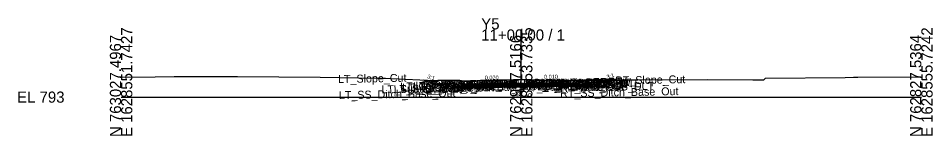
# Model space of a CAD drawing. Extents: x -26 to 203, y -10 to 6017.
# Drawn here: x -25.7 to 202.8, y 1990.3 to 2019.8 of the extents above; entities that cross this region are included whole.
import ezdxf

# ---------------------------------------------------------------- set-up
doc = ezdxf.new("R2010")
doc.units = 0
for name, color, linetype in [('Default', 7, 'Continuous'), ('Exist Cross Section Cell', 7, 'Continuous'), ('Exist XS Center Line Elevation Label', 7, 'Continuous'), ('Exist XS Ground Line', 7, 'Continuous'), ('Prop CMT Concrete Structures', 7, 'Continuous'), ('Prop CMT Pvmt Course 1', 7, 'Continuous'), ('Prop CMT Pvmt Course 2', 7, 'Continuous'), ('Prop CMT Pvmt Course 2 Wedge', 7, 'Continuous'), ('Prop CMT Pvmt Course 3', 7, 'Continuous'), ('Prop CMT Pvmt Course 3 Wedge', 7, 'Continuous'), ('Prop CMT Pvmt Surface', 7, 'Continuous'), ('Prop CMT Pvmt Surface Shoulder', 7, 'Continuous'), ('Prop CMT Pvmt Wedge Surface 2', 7, 'Continuous'), ('Prop CMT Pvmt Wedge Surface 3', 7, 'Continuous'), ('Prop CMT Shld Paved Course 1', 7, 'Continuous'), ('Prop CMT Shld Paved Course 2', 7, 'Continuous'), ('Prop CMT Shld Paved Course 3', 7, 'Continuous'), ('Prop CMT Slope Grass', 7, 'Continuous'), ('Prop CMT Subgrade Earthwork', 7, 'Continuous'), ('Prop XS SE Text', 7, 'Continuous'), ('Prop XS Side Slope Text', 7, 'Continuous'), ('Scratch_Level_0', 7, 'Continuous')]:
    doc.layers.add(name, color=color, linetype=linetype)

msp = doc.modelspace()

# ---------------------------------------------------------------- linework, layer by layer
at = {"layer": 'Exist Cross Section Cell'}
for p, q in [((100, 2000), (100, 2016.98)), ((0, 2000), (100, 2000)), ((100, 2000), (200, 2000))]:
    msp.add_line(p, q, dxfattribs=at)
at = {"layer": 'Exist XS Ground Line'}
msp.add_lwpolyline([(0, 2005.03), (8.53, 2005.09), (13.27, 2005.14), (29.06, 2005.14), (49.75, 2005), (64.15, 2004.73), (65.77, 2004.73), (66.1, 2004.74), (67.48, 2004.66), (74.7, 2004.31), (78.5, 2004.15), (79.12, 2004.21), (84.63, 2004.27), (85.57, 2004.05), (90.57, 2004.2), (98.03, 2004.44), (100, 2004.4), (113.3, 2004.16), (114.38, 2004.15), (115.84, 2004.18), (123.61, 2004.34), (129.16, 2004.36), (146.55, 2004.4), (157.88, 2004.33), (160.64, 2004.36), (161.06, 2004.79), (180.96, 2004.94), (183.03, 2004.97), (184.15, 2004.97), (200, 2005.09)], dxfattribs=at)
at = {"layer": 'Prop CMT Concrete Structures'}
for points in [[(83.35, 2003.24), (83.35, 2002.66), (85.35, 2002.66)], [(85.35, 2003.24), (84.35, 2003.16), (83.35, 2003.24)], [(85.35, 2002.66), (85.35, 2003.24)], [(114.68, 2003.1), (114.68, 2003.68)], [(116.68, 2003.68), (116.68, 2003.1), (114.68, 2003.1)], [(114.68, 2003.68), (115.68, 2003.6), (116.68, 2003.68)]]:
    msp.add_lwpolyline(points, dxfattribs=at)
at = {"layer": 'Prop CMT Pvmt Course 1'}
for points in [[(100, 2003.53), (85.35, 2003.24)], [(85.35, 2002.99), (100, 2003.28)], [(85.35, 2003.24), (85.35, 2002.99)], [(100, 2003.53), (85.57, 2003.25)], [(100, 2003.53), (114.38, 2003.68)], [(100, 2003.53), (114.68, 2003.68)], [(100, 2003.41), (100, 2003.53)], [(100, 2003.28), (100, 2003.53)], [(100, 2003.41), (100, 2003.53)], [(100, 2003.28), (100, 2003.53)], [(114.68, 2003.43), (100, 2003.28)], [(114.68, 2003.68), (114.68, 2003.43)]]:
    msp.add_lwpolyline(points, dxfattribs=at)
at = {"layer": 'Prop CMT Pvmt Course 2'}
for points in [[(100, 2003.28), (85.35, 2002.99)], [(85.35, 2002.99), (85.35, 2002.66)], [(85.35, 2002.99), (85.35, 2002.66)], [(85.35, 2002.66), (100, 2002.95)], [(100, 2003.28), (114.68, 2003.43)], [(100, 2002.95), (100, 2003.28)], [(100, 2002.95), (100, 2003.28)], [(114.68, 2003.1), (100, 2002.95)], [(114.68, 2003.43), (114.68, 2003.1)]]:
    msp.add_lwpolyline(points, dxfattribs=at)
at = {"layer": 'Prop CMT Pvmt Course 2 Wedge'}
for points in [[(100, 2003.28), (85.57, 2003)], [(100, 2003.28), (114.38, 2003.43)]]:
    msp.add_lwpolyline(points, dxfattribs=at)
at = {"layer": 'Prop CMT Pvmt Course 3'}
msp.add_line((116.68, 2003.1), (117.18, 2003.1), dxfattribs=at)
for points in [[(100, 2002.95), (85.35, 2002.66)], [(85.35, 2002.66), (85.35, 2002.32)], [(85.35, 2002.32), (100, 2002.62)], [(100, 2002.95), (114.68, 2003.1)], [(100, 2002.62), (100, 2002.95)], [(100, 2002.62), (100, 2002.95)], [(114.68, 2002.76), (100, 2002.62)], [(114.68, 2003.1), (114.68, 2002.76)]]:
    msp.add_lwpolyline(points, dxfattribs=at)
at = {"layer": 'Prop CMT Pvmt Course 3 Wedge'}
for points in [[(100, 2002.95), (85.57, 2002.66)], [(100, 2002.95), (114.38, 2003.09)]]:
    msp.add_lwpolyline(points, dxfattribs=at)
at = {"layer": 'Prop CMT Pvmt Surface'}
for points in [[(100, 2003.53), (85.35, 2003.24)], [(100, 2003.53), (85.57, 2003.25)], [(100, 2003.53), (114.68, 2003.68)], [(100, 2003.53), (114.38, 2003.68)]]:
    msp.add_lwpolyline(points, dxfattribs=at)
at = {"layer": 'Prop CMT Pvmt Surface Shoulder'}
for points in [[(85.35, 2003.24), (85.35, 2003.24)], [(114.68, 2003.68), (114.68, 2003.68)]]:
    msp.add_lwpolyline(points, dxfattribs=at)
at = {"layer": 'Prop CMT Pvmt Wedge Surface 2'}
for points in [[(100, 2003.28), (85.57, 2003)], [(100, 2003.28), (100, 2003.53)], [(100, 2003.28), (100, 2003.53)], [(100, 2003.28), (100, 2003.53)], [(100, 2003.28), (100, 2003.53)], [(100, 2003.28), (114.38, 2003.43)]]:
    msp.add_lwpolyline(points, dxfattribs=at)
at = {"layer": 'Prop CMT Pvmt Wedge Surface 3'}
for points in [[(100, 2002.95), (85.57, 2002.66)], [(100, 2002.95), (100, 2003.53)], [(100, 2002.95), (100, 2003.53)], [(100, 2002.95), (100, 2003.53)], [(100, 2002.95), (100, 2003.53)], [(100, 2002.95), (114.38, 2003.09)]]:
    msp.add_lwpolyline(points, dxfattribs=at)
at = {"layer": 'Prop CMT Shld Paved Course 1'}
for points in [[(85.35, 2003.24), (85.35, 2003.24)], [(85.35, 2002.99), (85.35, 2003.24)], [(114.68, 2003.68), (114.68, 2003.68)], [(114.68, 2003.43), (114.68, 2003.68)]]:
    msp.add_lwpolyline(points, dxfattribs=at)
at = {"layer": 'Prop CMT Shld Paved Course 2'}
for p, q in [((83.35, 2002.66), (85.35, 2002.66)), ((116.68, 2003.1), (114.68, 2003.1))]:
    msp.add_line(p, q, dxfattribs=at)
for points in [[(85.35, 2002.66), (85.35, 2002.99)], [(85.35, 2002.66), (85.35, 2002.99)], [(114.68, 2003.1), (114.68, 2003.43)]]:
    msp.add_lwpolyline(points, dxfattribs=at)
at = {"layer": 'Prop CMT Shld Paved Course 3'}
for p, q in [((82.51, 2002.32), (85.35, 2002.32)), ((117.52, 2002.76), (114.68, 2002.76))]:
    msp.add_line(p, q, dxfattribs=at)
for points in [[(85.35, 2002.66), (83.35, 2002.66), (82.85, 2002.66), (82.51, 2002.32)], [(85.35, 2002.32), (85.35, 2002.66)], [(114.68, 2002.76), (114.68, 2003.1)], [(114.68, 2003.1), (117.18, 2003.1), (117.18, 2003.1), (117.52, 2002.76)]]:
    msp.add_lwpolyline(points, dxfattribs=at)
at = {"layer": 'Prop CMT Slope Grass'}
for points in [[(83.35, 2003.24), (78.35, 2003.34), (75.54, 2004.28)], [(116.68, 2003.68), (121.68, 2003.78), (123.35, 2004.34)]]:
    msp.add_lwpolyline(points, dxfattribs=at)
at = {"layer": 'Prop CMT Subgrade Earthwork'}
for p, q in [((82.51, 2002.32), (81.55, 2003.28)), ((85.35, 2002.32), (82.51, 2002.32)), ((114.68, 2002.76), (117.52, 2002.76)), ((117.52, 2002.76), (118.48, 2003.72))]:
    msp.add_line(p, q, dxfattribs=at)
for points in [[(100, 2002.62), (85.35, 2002.32)], [(100, 2002.62), (114.68, 2002.76)]]:
    msp.add_lwpolyline(points, dxfattribs=at)

# ---------------------------------------------------------------- texts
at = {"layer": 'Default'}
msp.add_text('-', height=0.0001, dxfattribs=at).set_placement((0, 2000))
at = {"layer": 'Exist Cross Section Cell'}
for s, p in [('Y5', (90, 2016.98)), ('11+00.00 / 1', (90, 2014.18)), ('EL 793', (-26, 1998.6))]:
    msp.add_text(s, height=2.8, dxfattribs=at).set_placement(p)
for s, p in [('E 1628551.7427', (2.8, 1990)), ('E 1628553.7335', (102.8, 1990)), ('E 1628555.7242', (202.8, 1990)), ('N 763027.4967', (0, 1990)), ('N 762927.5166', (100, 1990)), ('N 762827.5364', (200, 1990))]:
    msp.add_text(s, height=2.8, rotation=90, dxfattribs=at).set_placement(p)
at = {"layer": 'Exist XS Center Line Elevation Label'}
msp.add_text('797.40', height=1.2, dxfattribs=at).set_placement((97.54, 1999.8))
at = {"layer": 'Prop XS SE Text'}
for s, rotation, p in [('0.020', 1.1458, (90.9, 2004.35)), ('0.010', 0.5729, (105.7, 2004.59))]:
    msp.add_text(s, height=1, rotation=rotation, dxfattribs=at).set_placement(p)
at = {"layer": 'Prop XS Side Slope Text'}
for rotation, p in [(341.5651, (76.43, 2004.77)), (18.4349, (121.53, 2004.52))]:
    msp.add_text('3:1', height=1, rotation=rotation, dxfattribs=at).set_placement(p)
at = {"layer": 'Scratch_Level_0'}
for s, p in [('LT_Slope_Cut', (54.24, 2003.52)), ('LT_PV2_OEEOP_W', (73.01, 2001.74)), ('LT_PV1_OEEOP_W', (73.57, 2001.88)), ('LT_PV1_OEEOP', (75.46, 2002.04)), ('LT_PV1_OEOT', (76.11, 2002.06)), ('LT_PS1_OEOP', (76.17, 2002.06)), ('RT_PV1_PGL_W', (89.86, 2002.21)), ('LT_PV1_PGL_W', (89.91, 2002.21)), ('PV2_PGL', (93.93, 2002.16)), ('PV1_PGL', (94.49, 2002.42)), ('RT_PS3_Shelf_Out', (101.74, 2001.79)), ('RT_PV2_OEEOP_W', (101.77, 2002.18)), ('RT_PV3_OEEOP_W', (101.77, 2001.84)), ('RT_PV1_OEEOP_W', (102.34, 2002.31)), ('RT_PV1_OEEOP', (104.23, 2002.47)), ('RT_PV2_OEOT', (104.83, 2002.23)), ('RT_PV3_OEOT', (104.83, 2001.9)), ('RT_PS2_OEOP', (105.15, 2002.23)), ('RT_PV1_OEOT', (105.4, 2002.5)), ('RT_PS1_OEOP', (105.46, 2002.5)), ('RT_PS3_OEOP', (105.49, 2001.89)), ('RT_GS_OS_CTL', (109.03, 2002.07)), ('RT_Slope_Cut', (123.48, 2003.16)), ('LT_SS_Ditch_Base_Out', (54.45, 1999.48)), ('LT_Sub_OSS_DLT', (65.09, 2000.92)), ('LT_Sub_Trench_Out', (68.14, 2000.98)), ('LT_GS_OS_CTL', (69.74, 2001.63)), ('LT_PS3_Shelf_Out', (70.26, 2001.36)), ('LT_PV3_OEEOP_W', (73.01, 2001.41)), ('LT_PS3_OEOP', (75.01, 2001.45)), ('LT_PS2_OEOP', (75.35, 2001.79)), ('LT_Sub_OEOT', (75.45, 2001.13)), ('LT_PV2_OEOT', (75.54, 2001.79)), ('LT_PV3_OEOT', (75.54, 2001.46)), ('Sub_PGL', (93.83, 2001.49)), ('PV3_PGL', (93.93, 2001.83)), ('RT_Sub_Trench_Out', (100.3, 2001.42)), ('RT_Sub_OEOT', (104.74, 2001.57)), ('RT_Sub_OSS_DLT', (109.74, 2001.36)), ('RT_SS_Ditch_Base_Out', (109.74, 1999.92))]:
    msp.add_text(s, height=2, rotation=1.1458, dxfattribs=at).set_placement(p)

doc.saveas('drawing.dxf')
